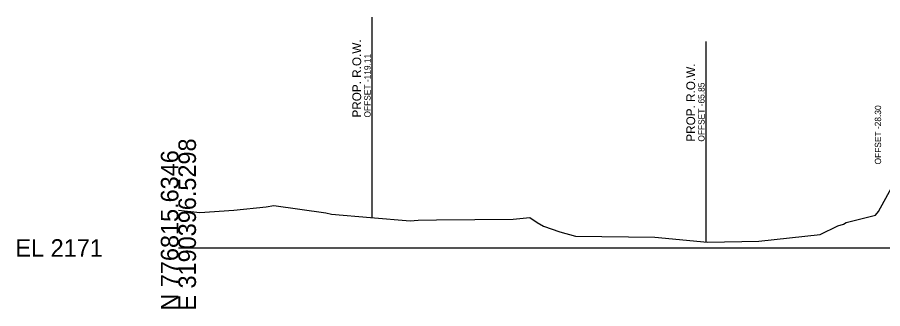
# Model space of a CAD drawing. Extents: x -26 to 303, y -25 to 5046.
# Drawn here: x -25.7 to 112.3, y 2490.3 to 2536.8 of the extents above; entities that cross this region are included whole.
import ezdxf

# ---------------------------------------------------------------- set-up
doc = ezdxf.new("R2010")
doc.units = 0
for name, color, linetype in [('DESIGN - ROW - Right-of-Way and Easement Labels', 7, 'Continuous'), ('DESIGN - ROW - Right-of-Way Linework', 7, 'Continuous'), ('DESIGN - SHEET - Light Grid', 7, 'Continuous'), ('DESIGN - TYPICAL - Slope Tie Text', 7, 'Continuous'), ('SURVEY - GROUND - Top of Ground', 7, 'Continuous')]:
    doc.layers.add(name, color=color, linetype=linetype)

msp = doc.modelspace()

# ---------------------------------------------------------------- linework, layer by layer
at = {"layer": 'DESIGN - ROW - Right-of-Way Linework'}
for p, q in [((30.89, 2504.82), (30.89, 2536.82)), ((84.15, 2500.97), (84.15, 2532.97))]:
    msp.add_line(p, q, dxfattribs=at)
at = {"layer": 'DESIGN - SHEET - Light Grid'}
msp.add_line((0, 2500), (150, 2500), dxfattribs=at)
at = {"layer": 'SURVEY - GROUND - Top of Ground'}
msp.add_lwpolyline([(0, 2506.06), (3.41, 2505.68), (8.86, 2506.02), (13.97, 2506.58), (15.23, 2506.77), (23.5, 2505.6), (24.4, 2505.4), (30.63, 2504.85), (36.94, 2504.34), (38.24, 2504.44), (41.14, 2504.51), (53.36, 2504.58), (56.02, 2504.84), (57.2, 2504.08), (58.22, 2503.46), (60.8, 2502.58), (63.31, 2501.9), (75.98, 2501.74), (84.37, 2500.95), (92.56, 2501.11), (102.34, 2502.16), (105.17, 2503.52), (106.04, 2503.78), (106.49, 2504.06), (111.16, 2505.25), (111.62, 2505.83), (113.7, 2509.62)], dxfattribs=at)

# ---------------------------------------------------------------- texts
at = {"layer": 'DESIGN - ROW - Right-of-Way and Easement Labels'}
for s, height, p in [('PROP. R.O.W.', 1.4, (29.14, 2520.82)), ('OFFSET -119.11', 1, (30.64, 2520.82)), ('PROP. R.O.W.', 1.4, (82.4, 2516.97)), ('OFFSET -65.85', 1, (83.9, 2516.97))]:
    msp.add_text(s, height=height, rotation=90, dxfattribs=at).set_placement(p)
at = {"layer": 'DESIGN - SHEET - Light Grid'}
for s, p in [('E 3190396.5298', (2.8, 2490)), ('N 776815.6346', (0, 2490))]:
    msp.add_text(s, height=2.8, rotation=90, dxfattribs=at).set_placement(p)
msp.add_text('EL 2171', height=2.8, dxfattribs=at).set_placement((-26, 2498.6))
at = {"layer": 'DESIGN - TYPICAL - Slope Tie Text'}
msp.add_text('OFFSET -28.30', height=1, rotation=90, dxfattribs=at).set_placement((112.06, 2513.33))

doc.saveas('drawing.dxf')
